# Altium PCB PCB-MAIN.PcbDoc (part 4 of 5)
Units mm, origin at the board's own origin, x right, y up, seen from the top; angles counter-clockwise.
Board outline 110 x 75 mm, 8 copper layers (F.Cu, In1.Cu, In2.Cu, In3.Cu, In4.Cu, In5.Cu, In6.Cu, B.Cu); 251 components, 185 nets, 1143 pads, 853 vias.
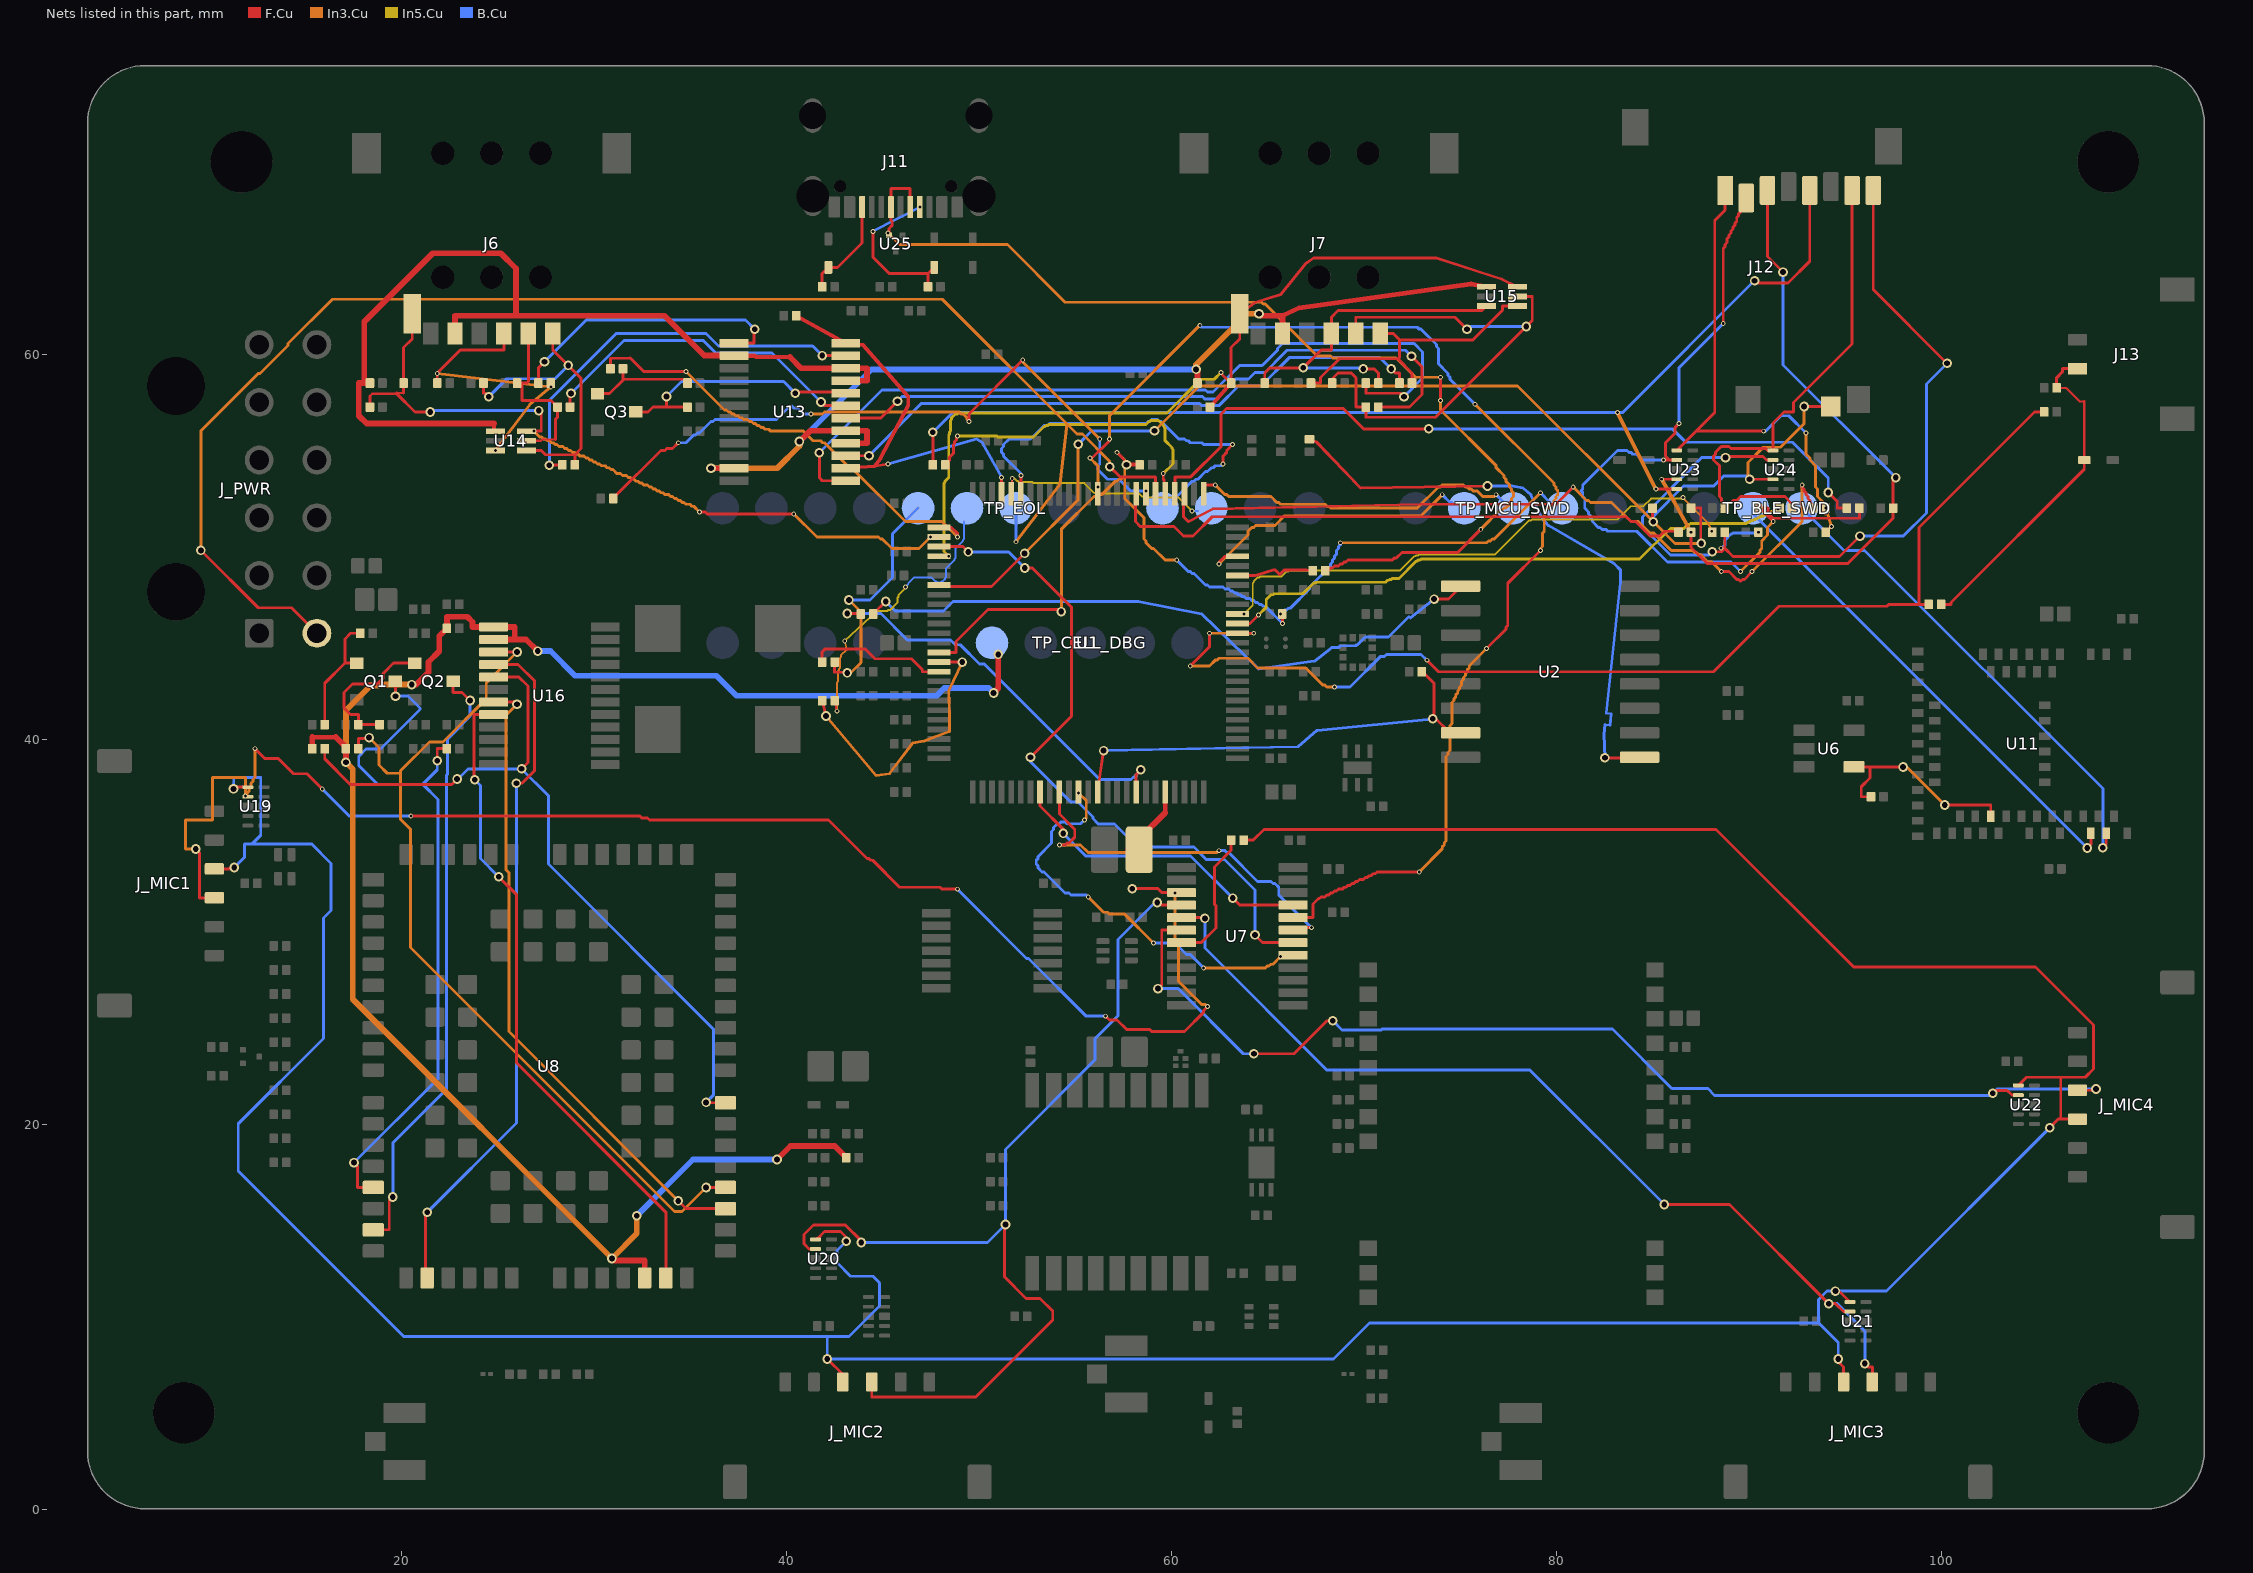
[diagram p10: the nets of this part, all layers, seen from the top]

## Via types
v1: diameter 0.5, hole 0.3, F.Cu to B.Cu, tented both sides, 579 vias
v2: diameter 0.25, hole 0.15, F.Cu to B.Cu, tented both sides, 274 vias

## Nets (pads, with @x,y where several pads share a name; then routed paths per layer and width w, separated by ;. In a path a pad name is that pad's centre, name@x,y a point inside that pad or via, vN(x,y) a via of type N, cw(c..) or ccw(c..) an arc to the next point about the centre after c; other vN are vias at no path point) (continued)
NOR_IO2_U2: R11.2 U2.9 | length 31.1
  F.Cu w0.15: R11.2@67.185,55.6 67.535,55.475 69.835,53.075 v1(76.435,53.175) ; v1(82.535,39.05) 84.285,39.05 84.305,39.05 U2.9@84.335,39.08
  B.Cu w0.15: v1(76.435,53.175) 77.735,53.175 78.285,53.075 78.685,52.725 79.285,51.475 79.585,51.125 83.035,49.125 83.335,48.825 83.335,48.125 82.603,41.369 82.862,41.341 82.797,40.744 82.539,40.772 82.485,40.275 v1(82.535,39.05)
NOR_IO3_U1: R12.1 U1.43 | length 21.1
  F.Cu w0.15: v1(43.16,46.55) R12.1@43.91,46.55 ; U1.43@58.185,37.275 58.16,37.3 58.16,38.175 v1(58.41,38.425)
  B.Cu w0.15: v1(43.16,46.55) 44.91,46.55 46.285,45.175 48.535,45.175 48.785,44.925 49.035,44.925 50.035,43.925 50.285,43.925 56.285,37.925 57.91,37.925 58.035,38.05 58.16,38.05 58.16,38.175 v1(58.41,38.425)
NOR_IO3_U2: R12.2 U2.1 | length 33.9
  F.Cu w0.15: R12.2@44.51,46.525 44.535,46.55 v1(45.16,47.175) ; v1(73.66,47.3) 74.41,47.3 75.035,47.925 U2.1@75.035,47.97
  B.Cu w0.15: v1(45.16,47.175) 45.66,46.675 48.16,46.675 48.66,47.175 58.285,47.175 61.585,46.525 64.535,43.675 67.435,44.075 68.285,44.725 ; 68.335,44.775 68.685,44.775 68.785,44.875 69.585,44.875 69.635,44.925 69.685,44.925 70.085,45.325 71.285,45.325 72.335,46.375 72.385,46.375 ; 72.435,46.325 v1(73.66,47.3)
NOR_NCS_U2: R7.2 U1.39 U2.7 | length 24.3
  F.Cu w0.15: U1.39@56.185,37.275 56.235,37.725 v1(56.485,39.425) ; R7.2@73.01,43.525 73.035,43.55 73.66,42.925 v1@73.66,41.175 ; v1@73.634,41.124 v1(73.585,41.075) v1@73.66,41.175 ; U2.7@75.035,40.35 75.035,40.3 74.535,40.3 v1@73.66,41.175
  B.Cu w0.15: v1(56.485,39.425) 66.585,39.625 67.585,40.475 v1(73.585,41.075)
NRF_RESET_N: R78.2 U6.4 U11.40 | length 10.7
  F.Cu w0.15: U6.4@95.485,38.575 96.312,38.575 ; R78.2@96.36,37.025 95.858,37.025 95.858,37.544 96.312,37.998 96.312,38.575 ; v1(98.028,38.575) 96.312,38.575 ; v1(100.191,36.602) 102.585,36.602 U11.40@102.585,36.025
  In3.Cu w0.15: v1(98.028,38.575) 98.217,38.575 v1(100.191,36.602)
NRF_SWCLK: TP_BLE_SWD.3 U11.53 | length 25.6
  F.Cu w0.15: v1(108.41,34.373) 108.585,34.548 U11.53@108.585,35.125
  B.Cu w0.15: TP_BLE_SWD.3@92.765,52.025 94.962,49.828 96.032,49.828 108.41,37.45 v1(108.41,34.373)
NRF_SWDIO: TP_BLE_SWD.2 U11.51 | length 25.7
  F.Cu w0.15: v1(107.599,34.363) 107.785,34.548 U11.51@107.785,35.125
  B.Cu w0.15: TP_BLE_SWD.2@90.225,52.025 90.225,51.737 v1(107.599,34.363)
NRST: C18.1 R1.2 TP_MCU_SWD.4 U1.14 | length 50.2
  F.Cu w0.15: U1.14@47.935,44.525 48.812,44.525 48.812,45.103 50.473,46.764 54.173,46.764 v1(54.289,46.648) ; v2(57.185,54.925) 57.785,54.325 C18.1@58.285,54.325 ; v1(57.676,54.275) C18.1@58.36,54.275 ; v2(65.785,46.025) R1.2@65.785,46.425
  In3.Cu w0.15: 54.285,50.925 55.985,52.625 56.185,52.625 56.285,52.725 56.385,52.725 57.085,53.425 57.185,53.425 57.285,53.525 57.385,53.525 57.485,53.625 57.585,53.625 ; v1(54.289,46.648) 54.289,50.888 ; v2(57.185,54.925) 57.585,54.525 57.585,52.525 58.585,51.525 58.585,50.425 58.685,50.325 58.685,50.225 58.985,49.925 59.085,49.925 59.685,49.325 v2(60.285,49.325) ; v2(68.785,50.225) 76.385,50.225 76.485,50.325 76.585,50.325 76.685,50.425 76.785,50.425 v2(79.185,52.825)
  B.Cu w0.15: v2(60.285,49.325) 60.885,48.725 60.985,48.725 61.085,48.625 61.185,48.625 61.785,48.025 61.885,48.025 61.985,47.925 62.685,47.925 62.785,47.825 62.985,47.825 63.085,47.725 63.185,47.725 63.285,47.625 63.385,47.625 63.485,47.525 63.585,47.525 63.685,47.425 63.785,47.425 63.885,47.325 64.085,47.325 64.185,47.225 64.285,47.225 64.385,47.125 64.485,47.125 64.585,47.025 64.685,47.025 64.785,46.925 64.885,46.925 v2(65.785,46.025) ; v2(65.685,46.525) 65.885,46.725 65.985,46.725 66.085,46.825 66.185,46.825 67.185,47.825 67.185,47.925 68.285,49.025 68.285,49.125 68.385,49.225 68.385,49.325 68.485,49.425 68.485,49.525 68.585,49.625 68.585,49.825 68.685,49.925 68.685,50.025 68.785,50.125 v2(68.785,50.225) ; v2(79.185,52.825) TP_MCU_SWD.4@79.685,52.325
PDM_CLK: U1.37 U7.17 | length 21
  In3.Cu w0.15: v2(55.185,37.225) 55.585,36.825 55.585,35.925 v2(55.485,35.825) ; v2(55.685,31.825) 56.485,31.025 56.685,31.025 56.785,30.925 57.585,30.925 v2(59.085,29.425) ; v2(61.685,28.125) 64.885,28.125 64.985,28.225 65.085,28.225 65.185,28.325 65.285,28.325 v2(65.685,28.725)
  B.Cu w0.15: v2(55.485,35.825) 55.285,35.625 54.585,35.625 54.485,35.725 54.285,35.725 54.185,35.625 54.085,35.625 53.885,35.425 53.885,35.325 53.785,35.225 53.785,34.625 53.085,33.925 53.085,33.825 52.985,33.725 52.985,33.525 53.085,33.425 53.085,33.325 53.285,33.125 53.385,33.125 54.485,32.025 54.685,32.025 54.785,31.925 55.585,31.925 v2(55.685,31.825) ; v2(59.085,29.425) 60.185,29.425 60.785,28.825 60.985,28.825 v2(61.685,28.125)
PDM_CLK_1V8_FANOUT: J_MIC1.3 J_MIC2.3 J_MIC3.3 J_MIC4.3 R17.2 U19.1 U20.1 U21.1 U22.1 | length 212.5
  F.Cu w0.15: J_MIC1.3@10.275,33.275 11.052,33.275 11.127,33.35 v1(11.308,33.35) ; v1(11.271,37.434) 11.361,37.525 U19.1@12.017,37.525 ; U20.1@41.517,14.025 41.571,14.078 41.631,14.078 41.981,14.428 42.816,14.428 43.117,14.127 v1(43.117,13.935) ; v1(42.123,7.812) 42.935,7 J_MIC2.3@42.935,6.615 ; R17.2@63.76,34.775 64.262,34.775 64.815,35.328 88.309,35.328 95.461,28.177 104.907,28.177 107.924,25.159 107.924,22.884 107.494,22.453 106.219,22.453 ; v1(94.51,11.341) 94.702,11.341 U21.1@95.267,10.775 ; v1(94.66,7.813) 94.66,7.667 94.935,7.392 J_MIC3.3@94.935,6.615 ; U22.1@104.017,22.025 104.446,22.453 106.219,22.453 ; v1(105.648,19.828) 106.094,20.275 106.219,20.275 ; J_MIC4.3@107.095,20.275 106.219,20.275 ; 106.219,20.275 106.219,22.453
  B.Cu w0.15: v1(11.271,37.434) 11.285,38.025 12.685,38.025 12.685,35.025 12.241,34.581 11.851,34.581 ; v1(11.308,33.35) 11.851,33.893 11.851,34.581 ; v1(43.117,13.935) 42.633,13.451 42.633,12.818 43.34,12.112 44.501,12.112 44.843,11.77 44.843,10.565 43.257,8.979 42.123,8.979 ; v1(94.66,7.813) 94.66,8.67 93.643,9.687 ; v1(105.648,19.828) 97.16,11.341 v1(94.51,11.341) 94.081,11.341 93.643,10.903 93.643,9.687 ; 11.851,34.581 15.318,34.581 16.337,33.561 16.337,31.116 15.953,30.732 15.953,24.473 11.519,20.039 11.519,17.573 20.113,8.979 42.123,8.979 ; 42.123,8.979 v1(42.123,7.812) 68.427,7.812 70.302,9.687 93.643,9.687
PDM_CLK_1V8_U7: R17.1 U7.7 | length 7.1
  F.Cu w0.15: U7.7@60.535,29.45 61.562,29.45 62.327,30.215 62.327,31.361 62.245,31.443 62.245,33.383 63.11,34.248 R17.1@63.11,34.775
PDM_DATA1: U1.33 U7.21 | length 16.1
  F.Cu w0.15: U1.33@53.185,37.275 53.185,36.544 54.392,35.337 v1(54.392,35.121) ; v1(63.196,31.76) 63.556,31.4 U7.21@66.335,31.4
  B.Cu w0.15: v1(54.392,35.121) 55.559,33.955 61.001,33.955 v1(63.196,31.76)
PDM_DATA1_1V8: J_MIC1.4 U7.3 U19.2 | length 80.6
  F.Cu w0.15: v1(9.305,34.314) 9.498,34.121 9.498,31.775 J_MIC1.4@10.275,31.775 ; v2(12.385,39.525) 12.885,39.025 13.585,39.025 14.385,38.225 15.085,38.225 v2(15.885,37.425) ; v2(20.485,36.025) 32.385,36.025 32.485,35.925 32.785,35.925 32.885,35.825 42.185,35.825 44.185,33.825 44.285,33.825 44.385,33.725 44.485,33.725 45.885,32.325 47.985,32.325 48.085,32.225 v2(48.885,32.225) ; v2(56.585,25.625) 56.785,25.425 57.185,25.425 57.685,24.925 58.885,24.925 58.985,24.825 60.685,24.825 61.685,25.825 61.685,25.925 v2(61.885,26.125) ; v1(57.977,32.251) 59.307,32.251 59.508,32.05 ; v2(60.185,32.025) 59.508,32.05 ; U7.3@60.535,32.05 59.508,32.05
  In3.Cu w0.15: v1(9.305,34.314) 8.785,34.314 8.785,35.825 10.185,35.825 10.185,38.025 11.885,38.025 v2(11.885,37.075) 11.985,37.125 11.985,37.225 12.085,37.325 12.085,37.425 12.185,37.525 12.185,37.725 12.285,37.825 12.285,37.925 12.385,38.025 v2(12.385,39.525) ; v2(60.185,32.025) 60.185,29.625 60.385,29.425 60.385,27.425 61.585,26.225 61.785,26.225 v2(61.885,26.125)
  B.Cu w0.15: v2(15.885,37.425) 17.285,36.025 v2(20.485,36.025) ; v2(48.885,32.225) 52.485,28.625 52.585,28.625 55.585,25.625 v2(56.585,25.625)
PDM_DATA2: U1.87 U7.20 | length 64.6
  F.Cu w0.15: v2(55.785,54.625) 55.885,54.625 56.785,55.525 v2(56.785,55.625) ; U7.20@66.335,30.75 67.362,30.75 67.362,31.449 67.649,31.736 ; 67.685,31.725 67.785,31.825 67.985,31.825 68.085,31.925 68.185,31.925 68.285,32.025 68.385,32.025 68.485,32.125 68.585,32.125 68.685,32.225 68.885,32.225 68.985,32.325 69.085,32.325 69.185,32.425 69.285,32.425 69.385,32.525 69.485,32.525 69.585,32.625 69.685,32.625 69.785,32.725 69.985,32.725 70.085,32.825 70.185,32.825 70.285,32.925 70.385,32.925 70.485,33.025 70.585,33.025 70.685,33.125 v2(72.885,33.125) ; v2(76.385,44.725) 77.385,45.725 77.385,45.825 77.485,45.925 77.485,48.125 v2(79.185,49.825)
  In3.Cu w0.15: v2(55.785,54.625) 56.185,54.225 v2(56.185,53.125) ; v2(56.785,55.625) 56.785,56.825 v2(61.485,61.525) ; v2(72.885,33.125) 74.085,34.325 74.085,34.425 74.185,34.525 74.185,34.625 74.285,34.725 74.285,39.125 74.385,39.225 74.385,39.325 74.485,39.425 74.485,40.725 74.585,40.825 74.585,41.925 74.685,42.025 74.685,42.125 74.785,42.225 74.785,42.325 74.885,42.425 74.885,42.525 74.985,42.625 74.985,42.725 75.085,42.825 75.085,43.025 75.185,43.125 75.185,43.225 75.285,43.325 75.285,43.425 75.385,43.525 75.385,43.625 75.485,43.725 75.485,43.825 v2(76.385,44.725) ; v2(75.785,57.425) 79.885,53.325 79.885,53.225 79.985,53.125 79.985,53.025 80.085,52.925 80.085,52.725 79.985,52.625 79.985,52.525 79.885,52.425 79.885,52.325 79.385,51.825 79.385,50.825 79.285,50.725 79.285,50.025 79.185,49.925 v2(79.185,49.825)
  B.Cu w0.15: v2(61.485,61.525) 61.585,61.425 72.785,61.425 72.885,61.325 72.985,61.325 73.785,60.525 73.785,60.425 73.885,60.325 73.885,59.525 74.385,59.025 74.385,58.925 74.485,58.825 74.485,58.725 v2(75.785,57.425)
PDM_DATA2_1V8: J_MIC2.4 U7.4 U20.2 | length 52.4
  F.Cu w0.15: U20.2@41.517,13.525 41.18,13.525 40.908,13.797 40.908,14.278 41.41,14.78 43.063,14.78 43.889,13.954 v1(43.889,13.863) ; J_MIC2.4@44.435,6.615 44.435,5.838 49.842,5.838 53.84,9.836 53.84,10.298 53.177,10.961 52.447,10.961 51.329,12.08 51.329,14.743 v1(51.385,14.799) ; v1(59.277,31.534) 59.374,31.534 59.508,31.4 U7.4@60.535,31.4
  B.Cu w0.15: v1(43.889,13.863) 50.449,13.863 v1(51.385,14.799) 51.385,18.703 56.039,23.357 56.039,24.457 57.227,25.645 57.227,29.611 59.15,31.534 v1(59.277,31.534)
PDM_DATA3: U1.35 U7.19 | length 18.8
  F.Cu w0.15: v2(54.185,34.525) 54.485,34.525 54.585,34.625 54.685,34.625 54.985,34.925 54.985,35.325 54.185,36.125 U1.35@54.185,36.825 ; U7.19@66.885,30.125 66.985,30.225 v2(67.285,30.225)
  In3.Cu w0.15: v2(54.185,34.525) 55.285,34.525 55.685,34.125 62.385,34.125 v2(62.485,34.225)
  B.Cu w0.15: v2(62.485,34.225) 62.785,34.225 62.885,34.125 62.985,34.125 64.485,32.625 65.185,32.625 65.285,32.525 65.385,32.525 65.585,32.325 65.585,31.925 v2(67.285,30.225)
PDM_DATA3_1V8: J_MIC3.4 U7.5 U21.2 | length 49.5
  F.Cu w0.15: U7.5@60.535,30.75 61.562,30.75 61.605,30.707 v1(61.748,30.707) ; v1(85.623,15.841) 89.014,15.841 v1(94.17,10.685) 94.52,10.685 94.93,10.275 U21.2@95.267,10.275 ; v1(96.041,7.57) 96.219,7.392 96.435,7.392 J_MIC3.4@96.435,6.615
  B.Cu w0.15: v1(61.748,30.707) 61.748,29.169 68.082,22.835 78.629,22.835 v1(85.623,15.841) ; v1(94.17,10.685) 94.625,10.685 96.041,9.27 v1(96.041,7.57)
PDM_DATA4: U1.3 U7.18 | length 36.1
  F.Cu w0.15: U1.3@47.935,50.025 49.181,50.025 v1(49.455,49.751) ; v1(52.39,48.914) 52.776,48.914 54.818,46.872 54.818,41.214 v1(52.685,39.082) ; v1(64.349,29.85) 64.749,29.45 U7.18@66.335,29.45
  B.Cu w0.15: v1(49.455,49.751) 51.552,49.751 v1(52.39,48.914) ; v1(52.685,39.082) 52.685,38.848 54.777,36.757 55.148,36.757 55.933,35.971 55.933,35.891 56.207,35.617 57.058,35.617 58.267,34.409 61.181,34.409 61.819,33.771 62.766,33.771 64.349,32.188 v1(64.349,29.85)
PDM_DATA4_1V8: J_MIC4.4 U7.6 U22.2 | length 59.3
  F.Cu w0.15: v1(59.309,27.058) 59.508,27.257 59.508,30.1 U7.6@60.535,30.1 ; v1(64.296,23.673) 66.385,23.673 68.098,25.386 v1(68.398,25.386) ; v1(102.683,21.619) 102.833,21.77 103.437,21.77 103.682,21.525 U22.2@104.017,21.525 ; J_MIC4.4@107.095,21.775 107.984,21.775 v1(108.053,21.844)
  B.Cu w0.15: v1(59.309,27.058) 60.36,27.058 63.745,23.673 v1(64.296,23.673) ; v1(68.398,25.386) 68.869,24.915 70.915,24.915 70.951,24.951 82.921,24.951 86.013,21.859 87.885,21.859 88.235,21.509 102.572,21.509 v1(102.683,21.619) 102.907,21.844 v1(108.053,21.844)
PWR_FAULT: R103.2 U1.82 | length 35.5
  F.Cu w0.15: R103.2@31.085,52.625 33.485,55.025 33.685,55.025 33.785,55.125 34.085,55.125 v2(34.385,55.425) ; v2(49.485,56.525) 49.485,56.925 v2(52.285,59.725)
  In3.Cu w0.15: v2(41.285,56.925) 41.885,56.925 41.985,57.025 48.985,57.025 49.085,56.925 49.185,56.925 49.385,56.725 49.385,56.625 v2(49.485,56.525) ; v2(52.285,59.725) 52.285,59.625 v2(56.285,55.625)
  B.Cu w0.15: v2(34.385,55.425) 34.785,55.425 35.185,55.825 35.285,55.825 35.385,55.925 35.485,55.925 36.085,56.525 36.185,56.525 36.285,56.625 39.485,56.625 40.085,57.225 40.185,57.225 40.285,57.325 40.385,57.225 40.585,57.225 40.885,56.925 v2(41.285,56.925) ; v2(56.285,55.625) 56.285,54.325 56.185,54.225 56.185,54.025 56.685,53.525 57.285,53.525 57.885,52.925 v2(58.685,52.925)
PWR_GOOD: J_PWR.7 TP_EOL.7 U1.81 | length 80.1
  F.Cu w0.15: v1(9.578,49.83) 12.558,46.85 14.28,46.85 J_PWR.7@15.605,45.525 ; v1(56.806,54.179) 57.333,53.652 59.185,53.652 U1.81@59.185,52.775
  In3.Cu w0.15: v1(9.578,49.83) 9.578,56.048 12.555,59.025 12.655,59.025 14.105,60.475 14.105,60.575 16.411,62.881 48.104,62.881 55.109,55.876 55.38,55.876 56.806,54.45 v1(56.806,54.179) ; v2(51.925,50.275) 54.225,53.275 54.585,56.4
  B.Cu w0.15: v2(51.925,50.275) TP_EOL.7@51.925,52.025
Q1_BASE: Q1.1 R24.2 R25.1 | length 6.4
  F.Cu w0.15: R24.2@16.01,40.775 16.01,41.302 16.01,42.927 17.058,43.975 ; Q1.1@17.685,43.975 17.058,43.975 ; R25.1@17.86,45.525 17.358,45.525 17.058,45.225 17.058,43.975
Q2_BASE: Q2.1 R26.2 R27.1 | length 7.8
  F.Cu w0.15: R27.1@18.86,40.775 R26.2@17.76,40.775 17.76,41.302 17.354,41.302 17.005,41.651 17.005,42.437 17.452,42.884 18.738,42.884 19.048,43.194 19.048,43.431 19.592,43.975 Q2.1@20.685,43.975
Q3_BASE: Q3.1 R46.2 R47.1 | length 5.6
  F.Cu w0.15: Q3.1@30.185,57.975 30.812,57.975 31.51,58.673 31.51,58.724 ; R46.2@31.51,59.275 31.51,58.724 ; R47.1@34.86,58.525 34.661,58.724 31.51,58.724
REV_STRAP0: TP_EOL.10 U1.95 | length 20.1
  F.Cu w0.15: U1.95@52.185,53.225 v2(52.185,53.725) ; v2(62.685,54.325) 62.685,54.725 62.885,54.925 62.885,55.025 v2(63.185,55.325)
  B.Cu w0.15: v2(52.185,53.725) 52.185,53.825 51.285,54.725 51.285,54.825 51.185,54.925 51.185,55.125 51.285,55.225 51.285,55.325 51.585,55.625 52.685,55.625 53.385,56.325 53.585,56.325 53.685,56.425 58.685,56.425 58.785,56.525 58.885,56.525 58.985,56.625 59.285,56.625 59.385,56.525 59.485,56.525 60.385,55.625 60.685,55.625 60.785,55.525 60.885,55.525 60.985,55.425 61.585,55.425 61.685,55.325 v2(63.185,55.325) ; TP_EOL.10@60.085,52.425 61.085,53.425 61.185,53.425 61.285,53.525 61.385,53.525 61.785,53.925 61.885,53.925 62.085,54.125 62.185,54.125 62.285,54.225 62.585,54.225 v2(62.685,54.325)
REV_STRAP1: TP_EOL.11 U1.96 | length 10.7
  F.Cu w0.1: U1.96@51.685,53.225 51.735,53.275 v2(51.735,53.575)
  In5.Cu w0.1: v2(51.735,53.575) 51.835,53.575 51.985,53.425 52.035,53.425 52.085,53.375 52.785,53.375 52.835,53.325 55.485,53.325 55.985,52.825 56.035,52.825 56.085,52.775 58.335,52.775 58.485,52.625 58.535,52.625 58.585,52.575 60.385,52.575 v2(61.085,51.875)
  B.Cu w0.1: v2(61.085,51.875) TP_EOL.11@61.385,51.875
SD_CK_CARD: J12.5 R79.2 U23.5 | length 60.2
  F.Cu w0.15: R79.2@47.61,54.275 47.61,55.966 v1(47.611,55.967) ; v2(85.185,53.025) U23.5@86.267,53.025 ; v1(90.313,63.846) 90.428,63.731 92.052,63.731 93.18,64.859 J12.5@93.18,68.535
  In3.Cu w0.2: v2(83.185,56.998) v2(85.185,53.025)
  B.Cu w0.15: v1(47.611,55.967) 48.642,56.998 83.464,56.998 v1(90.313,63.846)
SD_CK_U1: R79.1 U1.80 | length 16.5
  F.Cu w0.15: R79.1@48.335,54.375 48.485,54.525 48.485,54.675 48.685,54.875 48.685,55.325 48.735,55.375 48.735,55.475 48.835,55.575 48.835,55.725 v2(48.885,55.775) ; v2(59.585,53.825) 59.585,53.525 59.635,53.475 59.635,53.175 U1.80@59.685,53.125
  In5.Cu w0.15: v2(48.885,55.775) 50.935,55.775 50.985,55.725 52.835,55.725 53.385,56.275 53.435,56.275 53.485,56.325 53.585,56.325 53.635,56.375 58.685,56.375 58.835,56.525 58.885,56.525 58.935,56.575 59.335,56.575 59.435,56.475 59.485,56.475 59.585,56.375 59.585,56.325 59.635,56.275 59.635,56.225 59.685,56.175 59.685,55.525 60.035,55.175 60.035,55.125 60.085,55.075 60.085,54.325 v2(59.585,53.825)
SD_CMD_CARD: J12.3 R80.2 R85.2 U23.4 | length 36.4
  F.Cu w0.15: v2(85.485,53.525) U23.4@86.267,53.525 ; v2(87.01,50.775) 87.01,50.248 87.01,49.982 87.852,49.141 95.153,49.141 97.51,51.498 R85.2@97.51,52.025 97.51,53.475 v1(97.646,53.611) ; J12.3@90.98,68.535 90.98,65.099 v1(91.789,64.29)
  In3.Cu w0.2: v2(85.485,53.525) v2(87.01,50.775)
  B.Cu w0.15: v1(91.789,64.29) 91.789,59.468 v1(97.646,53.611)
SD_CMD_U1: R80.1 U1.83 | length 31
  F.Cu w0.15: U1.83@58.135,52.825 58.135,51.325 58.385,51.075 60.135,51.075 60.635,50.575 61.135,50.575 62.135,51.575 83.635,51.575 83.885,51.325 84.135,51.325 84.885,50.575 85.385,50.575 85.635,50.825 R80.1@86.385,50.825
SD_D0_CARD: J12.7 R81.2 R86.2 U24.1 | length 25.7
  F.Cu w0.15: R86.2@88.685,52.125 88.685,52.325 88.585,52.425 88.585,52.525 88.485,52.625 88.485,54.225 88.185,54.525 88.185,54.725 88.285,54.825 88.285,54.925 88.585,55.225 88.985,55.225 89.085,55.125 90.885,55.125 90.985,55.025 U24.1@91.285,55.025 ; R86.2@88.785,52.125 88.985,52.325 89.085,52.325 89.185,52.425 89.385,52.425 89.585,52.625 91.885,52.625 92.185,52.325 R81.2@92.185,52.125 ; U24.1@91.267,55.025 91.267,56.448 91.847,57.027 92.34,57.027 92.34,57.52 95.38,60.56 J12.7@95.38,68.535
SD_D0_U1: R81.1 U1.65 | length 30.3
  F.Cu w0.15: U1.65@63.885,46.025 64.085,46.025 v2(64.535,46.475)
  In5.Cu w0.15: v2(64.535,46.475) 64.935,46.875 64.935,47.275 65.185,47.525 65.285,47.525 65.335,47.575 66.835,47.575 67.385,48.125 67.485,48.125 67.535,48.175 71.135,48.175 71.235,48.275 71.285,48.275 71.335,48.325 71.435,48.325 71.485,48.375 71.835,48.375 72.735,49.275 72.785,49.275 72.835,49.325 72.935,49.325 72.985,49.375 84.335,49.375 85.935,50.975 86.635,50.975 86.835,51.175 86.935,51.175 86.985,51.225 89.885,51.225 89.935,51.275 89.985,51.275 90.035,51.325 90.085,51.325 90.135,51.375 90.235,51.375 90.285,51.425 90.335,51.425 90.385,51.475 90.435,51.475 90.485,51.525 90.535,51.525 90.585,51.575 90.635,51.575 90.685,51.625 90.785,51.625 90.835,51.675 90.885,51.675 90.935,51.725 90.985,51.725 91.035,51.775 91.085,51.775 91.135,51.825 91.185,51.825 91.235,51.875 91.335,51.875 91.385,51.925 91.435,51.925 91.485,51.975 v2(91.535,51.975)
SD_D1_CARD: J12.8 R82.2 R87.2 U24.2 | length 47.6
  F.Cu w0.15: v1(88.11,49.761) 88.577,49.761 88.76,49.944 ; v2(88.56,49.944) 88.76,49.944 ; R82.2@88.76,50.775 88.76,49.944 ; v1(88.804,54.652) 88.854,54.702 90.753,54.702 90.93,54.525 U24.2@91.267,54.525 ; v1(95.788,50.572) 94.726,49.51 89.194,49.51 88.76,49.944 ; J12.8@96.48,68.535 96.48,63.385 v1(100.317,59.549)
  B.Cu w0.15: v1(88.11,49.761) 87.935,49.586 85.938,49.586 84.482,51.042 84.482,51.567 87.568,54.652 v1(88.804,54.652) ; v2(88.56,49.944) 88.585,49.925 88.785,50.125 88.785,50.375 89.085,50.675 89.135,50.675 89.185,50.725 90.435,50.725 90.485,50.775 v2(90.51,50.775) ; v1(95.788,50.572) 98.038,50.572 99.239,51.774 99.239,58.471 v1(100.317,59.549)
SD_D1_U1: R82.1 U1.66 | length 28.4
  In3.Cu w0.1: v2(86.585,52.575) 87.885,51.275 87.885,51.225 87.935,51.175 87.935,51.125 87.985,51.075 87.985,51.025 88.035,50.975 88.035,50.925 88.085,50.875 v2(88.085,50.825)
  In5.Cu w0.1: v2(63.785,46.525) 64.235,46.975 64.235,48.125 64.285,48.175 64.285,48.225 64.485,48.425 64.585,48.425 64.635,48.475 65.735,48.475 65.985,48.725 66.085,48.725 66.135,48.775 71.885,48.775 72.635,49.525 72.685,49.525 72.735,49.575 72.835,49.575 72.885,49.625 76.835,49.625 78.585,51.375 78.685,51.375 78.735,51.425 83.185,51.425 83.885,52.125 84.535,52.125 84.935,52.525 86.535,52.525 v2(86.585,52.575)
SD_D2_CARD: J12.1 R83.2 R88.2 U23.1 | length 27.3
  F.Cu w0.15: U23.1@86.267,55.025 88.244,57.001 88.244,66.972 88.78,67.508 J12.1@88.78,68.535 ; 87.285,56.025 v2(90.785,56.025) ; R88.2@94.01,50.775 v2(94.31,51.075)
  In3.Cu w0.15: v2(92.985,55.925) 92.985,54.825 93.185,54.625 93.185,54.525 93.485,54.225 93.485,53.125 93.585,53.025 93.585,52.625 93.885,52.325 93.885,52.225 93.985,52.125 93.985,51.725 v2(94.01,52.025) v2(94.31,51.075)
  B.Cu w0.15: v2(90.785,56.025) 90.885,56.025 91.685,56.825 92.085,56.825 v2(92.985,55.925)
SD_D2_U1: R83.1 U1.78 | length 40.6
  F.Cu w0.15: U1.78@60.635,52.825 60.635,51.575 60.885,51.325 62.135,51.975 72.985,52.225 79.985,52.225 v2(80.885,53.125) ; v2(88.585,48.725) 88.985,48.725 89.385,48.325 89.485,48.325 89.585,48.225 89.685,48.325 89.785,48.325 v2(90.185,48.725) ; v2(92.785,53.225) 92.785,53.125 92.885,53.025 92.885,52.925 92.985,52.825 92.985,52.725 93.085,52.625 93.085,52.525 93.185,52.425 93.185,52.325 93.285,52.225 R83.1@93.285,52.125
  In3.Cu w0.15: v2(80.885,53.125) 81.585,52.425 81.685,52.425 81.785,52.325 82.885,52.325 83.885,51.325 84.285,51.325 84.885,50.725 85.085,50.725 85.985,49.825 87.085,49.825 87.185,49.725 87.285,49.725 87.385,49.625 87.485,49.625 87.885,49.225 88.085,49.225 v2(88.585,48.725) ; v2(90.185,48.725) 92.785,51.325 v2(92.785,53.225)
SD_D3_CARD: J12.2 R84.2 R89.2 U23.2 | length 42
  F.Cu w0.15: v2(85.585,54.525) U23.2@86.267,54.525 ; 85.885,54.525 85.685,54.725 85.685,55.425 86.185,55.925 86.185,56.225 v2(86.385,56.425) ; v2(88.685,61.625) 88.685,65.525 88.785,65.625 88.785,65.725 88.885,65.825 88.885,66.025 88.985,66.125 88.985,66.225 89.085,66.325 89.085,66.425 89.185,66.525 89.185,66.625 89.285,66.725 89.285,66.825 89.385,66.925 89.385,67.125 89.485,67.225 89.485,67.325 J12.2@89.685,67.525 ; R89.2@90.51,52.025 91.012,52.025 91.012,51.743 91.257,51.498 95.76,51.498 R84.2@95.76,52.025 ; R89.2@90.585,52.025 v2(91.285,51.325)
  In3.Cu w0.15: v2(89.585,48.725) 90.585,49.725 90.585,49.825 90.685,49.925 90.685,50.325 90.985,50.625 90.985,51.025 v2(91.285,51.325)
  B.Cu w0.15: v2(85.585,54.525) 84.485,54.525 84.185,54.825 83.985,54.825 83.885,54.925 83.785,54.925 83.685,55.025 83.185,55.025 81.385,53.225 81.385,53.025 81.285,52.925 81.385,52.825 81.385,52.625 81.485,52.525 81.485,52.025 81.685,51.825 81.685,51.725 81.785,51.625 81.785,51.525 81.885,51.425 81.885,51.325 82.185,51.025 82.285,51.025 82.385,50.925 82.585,50.925 82.685,50.825 84.185,50.825 85.785,49.225 89.085,49.225 v2(89.585,48.725) ; v2(86.385,56.425) 86.385,59.325 v2(88.685,61.625)
SD_D3_U1: R84.1 U1.79 | length 41
  F.Cu w0.15: U1.79@60.185,52.775 60.185,53.652 61.012,53.652 62.595,55.235 62.595,56.918 62.877,57.199 68.94,57.199 69.992,56.147 v1(73.384,56.147) ; v1(94.138,52.835) 94.608,52.366 94.608,52.025 R84.1@95.11,52.025
  B.Cu w0.15: v1(73.384,56.147) 86.032,56.147 86.733,55.446 92.281,55.446 94.138,53.589 v1(94.138,52.835)
SD_DET: C76.1 J12.CD R90.2 U1.7 U24.4 | length 66.5
  F.Cu w0.15: U1.7@47.935,48.025 48.008,47.952 50.658,47.952 v1(52.379,49.673) ; R90.2@85.01,52.025 85.01,51.356 v1(85.043,51.323) ; C76.1@87.01,52.025 87.512,52.025 87.512,50.226 v1(87.547,50.192) ; v1(90.052,53.525) U24.4@91.267,53.525 ; v1(92.885,57.305) J12.CD@94.27,57.305
  In3.Cu w0.15: v1(52.379,49.673) 55.162,52.456 v1(55.162,55.349) ; v1(59.129,56.042) 61.456,58.368 77.998,58.368 v1(85.043,51.323) 86.174,50.192 v1(87.547,50.192) ; v1(90.052,53.525) 89.978,53.599 89.978,54.401 90.766,55.19 91.665,55.19 92.885,56.41 v1(92.885,57.305)
  B.Cu w0.15: v1(55.162,55.349) 55.854,56.042 v1(59.129,56.042) ; v1(85.043,51.323) 85.043,51.591 86.621,53.169 88.192,53.169 88.712,53.69 89.887,53.69 v1(90.052,53.525)
SIM1_CLK_CONN: C55.1 J6.3 R51.2 U14.4 | length 15.9
  F.Cu w0.15: C55.1@24.26,58.525 24.26,57.998 24.348,57.998 v1(24.535,57.811) ; U14.4@26.49,55.025 27.262,55.025 27.485,54.802 29.01,54.802 ; J6.3@27.86,61.095 27.86,60.248 v1(28.666,59.444) 29.334,58.774 29.334,55.126 29.01,54.802 ; R51.2@29.01,54.275 29.01,54.802
  B.Cu w0.15: v1(24.535,57.811) 25.474,58.75 27.972,58.75 v1(28.666,59.444)
SIM1_CLK_MUX: R51.1 U13.23 | length 21.4
  F.Cu w0.15: v1(27.682,54.258) 27.841,54.258 27.858,54.275 R51.1@28.36,54.275 ; v1(41.86,59.95) U13.23@43.085,59.95
  B.Cu w0.15: v1(27.682,54.258) 27.682,57.621 31.157,61.096 35.825,61.096 36.477,60.443 41.366,60.443 v1(41.86,59.95)
SIM1_DATA_CONN: C56.1 J6.6 R52.2 U14.5 | length 9.3
  F.Cu w0.112: U14.5@26.49,55.525 27.243,55.525 27.318,55.6 28.012,55.6
  F.Cu w0.15: C56.1@26.01,58.525 26.261,58.525 ; J6.6@26.59,61.095 26.59,58.603 26.512,58.525 26.261,58.525 ; 28.012,55.6 28.012,56.65 28.11,56.748 28.11,57.267 R52.2@28.11,57.275 27.762,57.623 26.261,57.623 26.261,58.525
SIM1_DATA_MUX: R52.1 U13.19 | length 17.6
  F.Cu w0.15: R52.1@28.76,57.275 28.76,57.802 28.808,57.85 v1(28.808,57.988) ; v1(41.801,57.542) 41.992,57.35 U13.19@43.085,57.35
  B.Cu w0.15: v1(28.808,57.988) 31.563,60.744 35.679,60.744 36.331,60.092 39.251,60.092 v1(41.801,57.542)
SIM1_DET: C52.1 J6.7 R48.2 U1.2 U14.6 | length 39.8
  F.Cu w0.112: 18.36,57.85 18.479,57.969 19.754,57.969 ; 19.754,58 20.11,58
  F.Cu w0.15: R48.2@18.36,57.275 18.36,57.85 ; 19.754,58 19.754,57.969 20.704,57.019 v1(21.492,57.019) ; 20.11,58 C52.1@20.11,58.525 20.11,60.368 20.56,60.818 J6.7@20.56,62.12 ; U14.6@26.49,56.025 27.262,56.025 27.262,56.963 v1(27.132,57.092) ; v2(35.485,51.825) 35.785,51.825 35.885,51.725 v2(40.385,51.725)
  In3.Cu w0.15: v2(26.885,56.025) 27.185,55.725 27.285,55.725 27.385,55.625 27.485,55.625 27.585,55.525 27.685,55.525 27.785,55.425 27.885,55.425 27.985,55.325 28.085,55.325 28.185,55.225 28.385,55.225 28.485,55.125 28.585,55.125 28.685,55.025 28.785,55.025 28.885,54.925 28.985,54.925 29.085,54.825 29.185,54.825 29.285,54.725 29.485,54.725 29.585,54.625 29.685,54.625 29.785,54.525 29.885,54.525 29.985,54.425 30.085,54.425 30.185,54.325 30.285,54.325 30.385,54.225 30.585,54.225 30.685,54.125 30.785,54.125 30.885,54.025 30.985,54.025 31.185,53.825 31.385,53.825 31.485,53.725 31.685,53.725 31.785,53.625 31.885,53.625 31.985,53.525 32.085,53.525 32.185,53.425 32.285,53.425 32.385,53.325 32.485,53.325 32.585,53.225 32.785,53.225 32.885,53.125 32.985,53.125 33.085,53.025 33.185,53.025 33.285,52.925 33.385,52.925 33.485,52.825 33.585,52.825 33.685,52.725 33.885,52.725 33.985,52.625 34.085,52.625 34.185,52.525 34.285,52.525 34.385,52.425 34.485,52.425 34.585,52.325 34.685,52.325 34.785,52.225 34.985,52.225 35.085,52.125 35.185,52.125 v2(35.485,51.825) ; v2(40.385,51.725) 41.585,50.525 44.785,50.525 44.885,50.425 44.985,50.425 45.485,49.925 46.885,49.925 v2(47.485,50.525)
  B.Cu w0.15: v1(21.492,57.019) 21.565,57.092 v1(27.132,57.092)
SIM1_RST_CONN: C54.1 J6.2 R50.2 U14.3 | length 15.9
  F.Cu w0.15: C54.1@21.86,58.525 21.86,59.052 23.056,60.248 25.32,60.248 J6.2@25.32,61.095 ; v2(27.76,58.325) R50.2@27.76,58.525
  In3.Cu w0.15: v2(21.86,59.025) v2(27.76,58.325) 26.685,57.425 v2(24.88,55.025)
SIM1_RST_MUX: R50.1 U13.1 | length 15
  F.Cu w0.15: R50.1@27.11,58.525 27.11,59.305 v1(27.433,59.628) ; U13.1@37.285,60.6 38.312,60.6 38.312,61.277 v1(38.357,61.322)
  B.Cu w0.15: v1(27.433,59.628) 29.604,61.799 37.88,61.799 v1(38.357,61.322)
SIM1_VDD_CONN: C50.1 J6.1 U13.2 U13.21 U13.22 U14.1 | length 50.4
  F.Cu w0.225: 24.81,56.417 24.81,56.095 U14.1@24.88,56.025 ; U13.2@37.285,59.95 38.349,59.95 38.424,59.875 40.185,59.875
  F.Cu w0.3: C50.1@18.36,58.525 18.059,58.525 ; J6.1@22.78,61.095 22.78,62.017 25.955,62.017 ; 24.81,56.417 18.196,56.417 17.783,56.83 17.783,58.525 18.059,58.525 ; U13.2@37.285,59.95 35.734,59.95 33.667,62.017 25.955,62.017 ; 40.185,59.875 40.76,59.3 U13.22@43.085,59.3 44.187,59.3 44.187,58.65 U13.21@43.085,58.65 ; 18.059,58.525 18.059,61.707 21.627,65.275 25.157,65.275 25.955,64.478 25.955,62.017
SIM2_CLK_CONN: C58.1 J7.3 R54.2 U15.4 | length 15.9
  F.Cu w0.15: C58.1@67.26,58.525 67.762,58.525 67.762,58.81 68.739,59.786 71.776,59.786 ; J7.3@70.86,61.095 71.537,61.095 71.87,60.761 ; R54.2@72.51,58.525 72.51,58.964 72.51,59.051 72.51,59.052 71.776,59.786 ; U15.4@77.99,62.525 77.218,62.525 77.218,62.312 75.668,60.761 71.87,60.761 ; 71.776,59.786 71.87,59.881 71.87,60.761
SIM2_CLK_MUX: R54.1 U13.15 | length 31.8
  F.Cu w0.15: U13.15@43.085,54.75 v1(44.292,54.75) ; v1(71.437,59.26) 71.644,59.052 71.86,59.052 R54.1@71.86,58.525
  B.Cu w0.15: v1(44.292,54.75) 47.009,57.467 61.476,57.467 61.593,57.35 62.467,57.35 63.496,58.378 64.665,58.378 66.131,59.845 70.852,59.845 v1(71.437,59.26)
SIM2_DATA_CONN: C59.1 J7.6 R55.2 U15.5 | length 27
  F.Cu w0.15: C59.1@68.36,58.525 68.36,58.742 68.67,59.052 69.354,59.052 69.608,58.798 69.608,57.275 R55.2@70.11,57.275 70.11,56.748 73.734,56.748 v1(78.447,61.461) 78.762,61.776 78.762,63.025 U15.5@77.99,63.025 ; J7.6@69.59,61.095 69.59,61.942 74.742,61.942 v1(75.365,61.319)
  B.Cu w0.15: v1(75.365,61.319) 75.508,61.461 v1(78.447,61.461)
SIM2_DATA_MUX: R55.1 U13.18 | length 35.8
  F.Cu w0.15: U13.18@43.085,56.7 44.892,56.7 v1(45.774,57.582) ; R55.1@70.76,57.275 72.382,57.275 73.03,57.922 73.03,59.371 v1(72.486,59.915)
  B.Cu w0.15: v1(45.774,57.582) 46.011,57.819 61.621,57.819 61.739,57.701 62.322,57.701 63.35,58.73 64.008,58.73 64.36,59.082 64.871,59.082 65.875,60.086 66.02,60.231 72.17,60.231 v1(72.486,59.915)
SIM2_DET: C53.1 J7.7 R49.2 U1.4 U15.6 | length 44.4
  F.Cu w0.15: U1.4@48.385,49.525 v2(48.435,49.525) ; v2(62.585,59.075) 62.585,59.025 C53.1@63.035,58.575 ; C53.1@63.11,58.525 63.11,60.368 63.56,60.818 63.56,62.058 J7.7@63.56,62.12 64.385,62.725 65.685,63.125 66.985,64.725 67.385,65.025 73.785,65.025 77.185,63.925 U15.6@77.99,63.525
  F.Cu w0.2: R49.2@62.01,57.275 C53.1@63.11,58.525
  In5.Cu w0.15: v2(48.435,49.525) 48.185,49.775 48.185,53.325 48.235,53.375 48.235,53.425 48.435,53.625 48.435,55.825 48.485,55.875 48.485,55.975 48.535,56.025 48.535,56.575 48.585,56.625 48.585,56.725 48.785,56.925 48.885,56.925 48.935,56.975 59.785,56.975 61.535,58.725 62.235,58.725 v2(62.585,59.075)
SIM2_RST_CONN: C57.1 J7.2 R53.2 U15.3 | length 19
  F.Cu w0.15: C57.1@64.86,58.525 64.86,59.052 65.125,59.317 v1(66.863,59.317) 67.794,60.248 68.32,60.248 J7.2@68.32,61.095 68.32,61.942 68.672,62.293 76.148,62.293 U15.3@76.38,62.525 ; v1(69.983,59.26) 70.552,59.26 70.76,59.052 R53.2@70.76,58.525
  B.Cu w0.15: v1(66.863,59.317) 69.926,59.317 v1(69.983,59.26)
SIM2_RST_MUX: R53.1 U13.13 | length 42.1
  F.Cu w0.15: v1(41.713,54.909) 41.713,53.603 41.866,53.45 U13.13@43.085,53.45 ; R53.1@70.11,58.525 70.11,57.998 71.903,57.998 v1(72.092,57.809)
  B.Cu w0.15: v1(41.713,54.909) 44.976,58.172 61.766,58.172 61.884,58.053 62.176,58.053 63.556,59.433 64.725,59.433 65.524,60.232 65.524,60.32 65.786,60.582 72.622,60.582 73.062,60.142 73.062,58.78 v1(72.092,57.809)
SIM2_VDD_CONN: C51.1 J7.1 U13.11 U13.16 U13.17 U15.1 | length 52.5
  F.Cu w0.25: 65.78,62.017 66.63,62.425 75.58,63.675 U15.1@76.38,63.525
  F.Cu w0.3: v1(36.082,54.102) 36.084,54.1 U13.11@37.285,54.1 ; v1(40.675,55.488) 41.238,56.05 41.983,56.05 U13.17@43.085,56.05 44.187,56.05 44.187,55.4 U13.16@43.085,55.4 ; v1(61.29,59.235) 61.36,59.164 C51.1@61.36,58.525 ; v1(64.561,62.126) 64.671,62.017 65.78,62.017 65.78,62.015 65.78,61.891 J7.1@65.78,61.095
  In3.Cu w0.3: v1(36.082,54.102) 39.526,54.102 40.675,55.251 v1(40.675,55.488) ; v1(61.29,59.235) 61.29,59.478 63.938,62.126 v1(64.561,62.126)
  B.Cu w0.3: v1(40.675,55.488) 44.422,59.235 v1(61.29,59.235)
SIM_MUX_EN: R46.1 U1.1 | length 23.2
  F.Cu w0.15: R46.1@30.86,59.275 30.86,59.802 31.885,59.825 32.585,59.125 v2(34.785,59.125) ; U1.1@48.385,51.025 48.585,51.025 48.885,50.725 v2(48.885,50.525)
  In3.Cu w0.15: v2(34.785,59.125) 36.785,57.125 36.885,57.125 36.985,57.025 37.085,57.025 37.185,56.925 37.285,56.925 37.385,56.825 37.485,56.825 37.585,56.725 37.685,56.725 37.785,56.625 37.985,56.625 38.085,56.525 38.185,56.525 38.285,56.425 38.385,56.425 38.485,56.325 38.585,56.325 38.685,56.225 38.785,56.225 38.885,56.125 39.085,56.125 39.185,56.025 40.885,56.025 41.385,55.525 41.785,55.525 41.885,55.425 41.985,55.425 43.285,54.125 43.385,54.125 46.185,51.325 48.085,51.325 v2(48.885,50.525)
SIM_MUX_SEL: R45.1 U1.97 U13.14 U13.24 | length 21.8
  F.Cu w0.15: 44.585,54.2 v2(45.285,54.325) ; U1.97@51.185,52.775 v2(51.185,53.625)
  F.Cu w0.2: R45.1@40.51,62.025 U13.24@43.085,60.6 43.985,60.5 46.335,57.8 46.335,57.35 44.885,54.6 44.585,54.2 U13.14@43.085,54.1
  B.Cu w0.15: v2(45.285,54.325) 49.885,55.625 50.185,55.425 v2(51.185,53.625)
SMPS_SW: L1.1 U1.46 | length 4.1
  F.Cu w0.225: 59.685,36.2 U1.46@59.685,37.275
  F.Cu w0.3: L1.1@57.76,34.275 L1.1@58.335,34.275 58.337,34.852 59.685,36.2
SWCLK: TP_MCU_SWD.3 U1.76 | length 16.9
  F.Cu w0.15: U1.76@61.685,53.225 v2(62.285,53.225)
  In3.Cu w0.15: v2(62.285,53.225) 62.785,52.725 62.885,52.725 62.985,52.625 65.185,52.625 65.485,52.325 65.585,52.325 65.685,52.225 67.985,52.225 68.085,52.125 68.185,52.125 68.285,52.025 72.785,52.025 73.885,53.125 73.985,53.125 74.085,53.225 75.185,53.225 75.285,53.125 75.385,53.125 75.485,53.025 75.585,53.025 75.685,52.925 75.885,52.925 76.185,52.625 76.785,52.625 v2(76.885,52.725)
  B.Cu w0.15: v2(76.885,52.725) TP_MCU_SWD.3@77.185,52.425
SWDIO: TP_MCU_SWD.2 U1.72 | length 14.6
  F.Cu w0.15: v2(62.485,49.125) 62.485,49.225 62.785,49.525 U1.72@62.985,49.525
  In3.Cu w0.15: v2(62.485,49.125) 63.985,50.625 63.985,50.825 64.185,51.025 64.285,51.025 64.385,51.125 65.385,51.125 65.885,51.625 72.985,51.625 v2(74.085,52.725)
  B.Cu w0.15: v2(74.085,52.725) 74.485,52.325 TP_MCU_SWD.2@74.585,52.325
TAMPER_IN_CONN: D9.1 J13.1 R99.2 R100.1 | length 17.6
  F.Cu w0.112: R99.2@106.01,58.275 106.493,58.275 107.193,57.575 107.445,57.575
  F.Cu w0.15: R100.1@100.01,47.025 100.512,47.025 100.512,47.115 107.445,54.048 D9.1@107.445,54.525 107.445,57.575 ; R99.2@106.01,58.275 106.01,58.802 106.318,59.11 106.318,59.275 J13.1@107.095,59.275
TAMPER_IN_U1: C78.1 R100.2 U1.64 | length 59.9
  F.Cu w0.15: v2(60.985,43.825) 61.985,44.825 v2(61.985,45.525) ; U1.64@63.885,45.525 v2(64.285,45.525) ; v2(73.285,44.125) 73.885,43.525 88.185,43.525 91.585,46.925 97.185,46.925 97.285,47.025 98.485,47.025 ; 98.087,47.025 98.858,47.025 ; R100.2@99.36,47.025 98.858,47.025 ; C78.1@105.36,57.025 104.858,57.025 98.858,51.025 98.858,47.025
  In3.Cu w0.15: v2(60.985,43.825) 61.985,43.825 62.285,44.125 62.385,44.125 62.485,44.225 63.985,44.225 64.485,43.725 66.985,43.725 67.885,42.825 67.985,42.825 68.085,42.725 v2(68.485,42.725) ; v2(61.985,45.525) v2(64.285,45.525)
  B.Cu w0.15: v2(68.485,42.725) 69.285,42.725 70.885,44.325 71.085,44.325 71.185,44.425 72.985,44.425 v2(73.285,44.125)
TEST_UART_RX_TP: R102.1 TP_EOL.6 | length 14.7
  F.Cu w0.1: R102.1@42.585,41.925 42.585,41.575 42.635,41.525 v2(42.635,41.475)
  In3.Cu w0.1: v2(42.635,41.475) 42.635,42.975 42.685,43.025 42.685,43.575 42.735,43.625 42.735,43.675 42.785,43.725 42.785,44.225 42.835,44.275 42.835,44.375 43.135,44.675 v2(43.035,45.125)
  In5.Cu w0.1: v2(43.035,45.125) 44.685,46.675 45.235,46.675 45.285,46.725 45.385,46.725 45.785,47.125 45.785,47.375 45.835,47.425 45.835,47.525 46.185,47.875 v2(46.185,47.925)
  B.Cu w0.1: v2(46.185,47.925) 46.335,48.075 46.335,48.125 46.635,48.425 47.535,48.425 47.735,48.225 47.785,48.225 47.835,48.175 48.035,48.175 48.085,48.225 48.135,48.225 48.235,48.325 48.235,48.375 48.285,48.425 48.285,48.875 48.735,49.325 48.735,49.375 48.785,49.425 48.785,49.925 49.185,50.325 49.185,50.375 49.235,50.425 TP_EOL.6@49.235,51.325
TEST_UART_RX_U1: R102.2 U1.15 | length 14.6
  F.Cu w0.15: R102.2@41.86,42.025 v1(42.06,41.225) ; U1.15@47.935,44.025 v1(49.135,44.025)
  In3.Cu w0.15: v1(42.06,41.225) 44.66,38.125 45.36,38.225 46.56,39.825 47.16,39.925 48.485,40.425 48.485,41.225 48.435,42.525 v1(49.135,44.025)
TEST_UART_TX_TP: R101.2 TP_EOL.5 | length 12.5
  F.Cu w0.15: R101.2@42.51,44.025 42.51,43.498 43.134,43.498 v1(43.167,43.465)
  In3.Cu w0.15: v1(43.167,43.465) 43.34,43.465 43.87,43.994 43.87,46.631 v1(43.249,47.252)
  B.Cu w0.15: v1(43.249,47.252) 44.34,47.252 45.509,48.421 45.509,50.689 TP_EOL.5@46.845,52.025
TEST_UART_TX_U1: R101.1 U1.16 | length 7.2
  F.Cu w0.15: R101.1@41.86,44.025 41.86,44.552 42.023,44.715 44.093,44.715 44.608,44.2 46.499,44.2 47.058,43.641 47.058,43.525 U1.16@47.935,43.525
U8_MAIN_DTR_1V8: U8.30 U16.8 | length 34.4
  F.Cu w0.15: v1(23.81,37.906) 23.758,37.958 23.758,41.3 U16.8@24.785,41.3 ; v1(25.052,32.866) 25.985,31.933 25.985,23.188 33.735,15.438 U8.30@33.735,12.025
  B.Cu w0.15: v1(23.81,37.906) 24.097,37.619 24.097,33.82 v1(25.052,32.866)
U8_MAIN_RI_1V8: R31.2 U8.39 U16.5 | length 40.7
  F.Cu w0.15: R31.2@16.01,39.525 16.01,38.998 17.337,37.671 22.607,37.671 v1(22.889,37.952) ; U16.5@24.785,43.25 26.097,43.25 26.569,42.779 26.569,38.803 v1(26.242,38.477) ; v1(35.829,21.145) 35.849,21.125 U8.39@36.835,21.125
  B.Cu w0.15: v1(22.889,37.952) 22.932,37.952 23.457,38.477 v1(26.242,38.477) 27.643,37.077 27.643,33.527 36.203,24.967 36.203,21.519 v1(35.829,21.145)
U8_MAIN_RXD_1V8: U8.34 U16.7 | length 33.6
  F.Cu w0.15: U16.7@24.785,41.95 25.888,41.95 v1(26.001,41.837) ; v1(34.379,16.027) 34.781,15.625 U8.34@36.835,15.625
  In3.Cu w0.15: v1(26.001,41.837) 25.427,41.263 25.427,33.237 25.582,33.082 25.582,24.824 v1(34.379,16.027)
U8_MAIN_TXD_1V8: R30.2 U8.35 U16.3 | length 46.3
  F.Cu w0.15: R30.2@17.76,39.525 17.76,40.052 18.268,40.052 v1(18.318,40.102) ; U16.3@24.785,44.55 v1(26.005,44.55) ; v1(35.827,16.725) U8.35@36.835,16.725
  In3.Cu w0.15: v1(18.318,40.102) 18.833,39.586 18.833,38.676 19.262,38.248 19.951,38.248 ; v1(26.005,44.55) 24.402,42.947 24.402,42.12 22.154,39.873 21.448,39.873 19.951,38.375 19.951,38.248 ; v1(35.827,16.725) 34.581,15.48 34.181,15.48 20.464,29.197 20.464,35.343 19.951,35.855 19.951,38.248
U8_PWRKEY_N: C48.1 Q1.3 U8.15 | length 37.4
  F.Cu w0.15: v1(17.532,18.015) 17.708,17.839 17.708,16.725 U8.15@18.535,16.725 ; v1(19.686,42.255) 19.685,42.448 Q1.3@19.685,43.025 ; v1(21.856,38.894) 21.858,38.896 21.858,39.525 21.859,39.525 21.946,39.525 C48.1@22.36,39.525
  B.Cu w0.15: v1(17.532,18.015) 21.891,22.373 21.891,36.887 21.102,37.676 ; v1(19.686,42.255) 20.345,42.255 20.969,41.632 20.969,41.57 18.903,39.504 18.16,39.504 17.779,39.122 17.779,38.647 18.75,37.676 21.102,37.676 ; v1(21.856,38.894) 21.856,38.43 21.102,37.676
U8_RESET_N: Q2.3 U8.17 | length 31.7
  F.Cu w0.15: U8.17@18.535,14.525 19.362,14.525 19.362,16.039 v1(19.55,16.227) ; Q2.3@22.685,43.025 22.685,42.448 23.142,42.448 v1(23.563,42.027)
  B.Cu w0.15: v1(19.55,16.227) 19.55,19.038 22.34,21.828 22.34,38.149 22.383,38.191 22.383,40.017 23.563,41.197 v1(23.563,42.027)
U8_STATUS_1V8: U8.20 U16.4 | length 36.1
  F.Cu w0.15: U8.20@21.335,12.025 21.241,12.119 21.241,15.342 v1(21.335,15.436) ; U16.4@24.785,43.9 25.812,43.9 26.061,43.9 26.92,43.04 26.92,38.386 26.262,37.728 v1(25.97,37.728)
  B.Cu w0.15: v1(21.335,15.436) 25.97,20.071 v1(25.97,37.728)
U8_VDD_EXT_1V8: C33.1 R30.1 R31.1 R41.1 TP_CELL_DBG.1 U8.29 U16.1 U16.2 | length 98.1
  F.Cu w0.225: 15.36,40.126 16.585,40.126
  F.Cu w0.3: R31.1@15.36,39.525 15.36,40.126 ; 16.585,40.126 17.11,39.601 R30.1@17.11,39.525 17.11,38.824 v1(17.112,38.822) ; v1(20.534,42.854) 20.765,42.854 21.41,43.499 21.41,44.03 21.965,44.586 21.965,45.381 C33.1@22.36,45.775 22.36,46.377 23.42,46.377 23.683,46.114 23.683,45.85 U16.1@24.785,45.85 25.887,45.85 25.887,45.2 ; U16.2@24.785,45.2 25.887,45.2 ; v1(27.078,44.595) 26.473,45.2 25.887,45.2 ; v1(30.935,13.036) 31.044,12.927 32.635,12.927 U8.29@32.635,12.025 ; v1(39.513,18.178) 40.212,18.877 42.508,18.877 R41.1@43.11,18.275 ; v1(50.77,42.42) 51.01,42.661 v1(51.01,44.425)
  In3.Cu w0.3: v1(20.534,42.854) 20.527,42.86 18.82,42.86 18.769,42.809 18.399,42.809 17.112,41.522 v1(17.112,38.822) 17.462,38.472 17.462,26.509 v1(30.935,13.036) 32.229,14.329 v1(32.229,15.253)
  B.Cu w0.3: v1(27.078,44.595) 27.74,44.595 29.021,43.314 36.374,43.314 37.406,42.282 47.812,42.282 48.202,42.672 50.518,42.672 v1(50.77,42.42) ; v1(32.229,15.253) 35.155,18.178 v1(39.513,18.178)
U13_EN_N: Q3.3 R44.2 U13.20 | length 13.3
  F.Cu w0.15: Q3.3@32.185,57.025 32.812,57.025 33.062,57.275 33.772,57.275 ; v1(33.772,57.826) 33.772,57.275 ; R44.2@34.86,57.275 33.772,57.275 ; v1(40.466,58) 40.534,58.069 43.017,58.069 U13.20@43.085,58
  B.Cu w0.15: v1(33.772,57.826) 34.553,58.607 39.859,58.607 v1(40.466,58)
USB_CC1: D7.1 J11.A5 R93.1 | length 8.5
  F.Cu w0.15: v2(44.498,66.408) 44.498,65.06 45.348,64.21 47.36,64.21 ; R93.1@47.36,63.525 47.36,64.21 ; D7.1@47.685,64.535 47.36,64.21
  B.Cu w0.15: v2(44.498,66.408) v2(46.935,67.67)
USB_CC2: D8.1 J11.B5 R94.1 | length 5.3
  F.Cu w0.15: R94.1@41.86,63.525 41.86,64.21 D8.1@42.185,64.535 42.662,64.535 43.935,65.808 J11.B5@43.935,67.67
USB_DM_CONN: J11.A7 J11.B7 R92.2 U25.2 | length 55.4
  F.Cu w0.15: R92.2@68.085,48.825 68.185,48.825 68.285,48.925 68.385,48.925 68.485,49.025 68.685,49.025 68.785,49.125 68.885,49.125 68.985,49.225 69.085,49.225 69.185,49.325 71.485,49.325 71.585,49.425 71.685,49.425 71.985,49.725 74.885,49.725 v2(76.085,50.925) ; v2(73.985,57.625) v2(73.985,58.825)
  F.Cu w0.154: U25.2@45.335,66.2 45.335,66.558 45.502,66.725 45.502,66.908 45.435,66.975 J11.A7@45.435,67.67 45.435,68.625 46.435,68.625 J11.B7@46.435,67.67
  In3.Cu w0.15: v2(45.285,66.325) 45.885,65.725 51.485,65.725 54.485,62.725 64.685,62.725 64.785,62.625 64.885,62.625 67.585,59.925 68.285,59.925 68.385,59.825 71.685,59.825 72.685,58.825 v2(73.985,58.825) ; v2(73.985,57.625) 73.985,57.125 76.885,54.225 76.885,54.125 77.285,53.725 77.285,53.625 77.385,53.525 77.385,53.425 77.585,53.225 77.585,53.125 77.685,53.025 77.685,52.925 77.785,52.825 77.785,52.625 77.685,52.525 77.685,52.425 77.585,52.325 77.585,52.225 77.385,52.025 77.285,52.025 77.185,51.925 77.085,51.925 v2(76.085,50.925)
USB_DM_U1: R92.1 U1.70 | length 4.2
  F.Cu w0.154: U1.70@63.435,48.525 64.385,48.525 64.885,48.675 65.285,48.818 65.385,48.818 65.635,48.57 65.885,48.818 67.035,48.818 R92.1@67.36,48.775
